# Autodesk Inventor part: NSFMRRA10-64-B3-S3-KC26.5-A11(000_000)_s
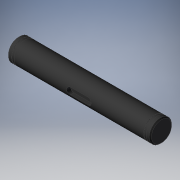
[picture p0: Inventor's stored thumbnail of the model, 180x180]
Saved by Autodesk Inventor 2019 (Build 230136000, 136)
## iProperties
Created: 2022-11
Part Number: NSFMRRA10-64-B3-S3-KC26.5-A11(000_000)_s
Material: Generic
Catalog Web Link: www.cadenas.de
Description: NSFMRR, SFMRR, PSFMRR, SSFMRR, NSFHRR, SFHRR, PSFHRR, SSFHRR, NSFRR, SFRR, PSFRR, SSFRR, NSFMRRA, SFMRRA, PSFMRRA, SSFMRRA, NSFHRRA, SFHRRA, PSFHRRA, SSFHRRA, N
Vendor: MISUMI
Document SubType Name: Modeling
Designer: psAdmin
Manufacturer: MISUMI
Mass: 4.95111 g
Surface Area: 22.1095 cm^2
Volume: 4.95111 cm^3
Density: 1 g/cm^3
Appearance: PSOLRGB-175-175-175
Category: PARTsolutions
Company: MISUMI
Title: NSFMRRA10-64-B3-S3-KC26.5-A11
Author: Cadenas PARTsolutions
Comments: Rotary Shafts - Retaining Ring Grooves on Both Ends - Standard
PSOL_IDENT_0: {$CADENAS_DATA/23d-libs/misumi/metric/11_rotary_shafts/11_components/psfrra/psfrra.prj},808 {VTYP=3D
PSOL_IDENT_1: },{NB=NSFMRRA10-64-B3-S3-KC26.5-A11(000_000)_s},{LINA=NSFMRRA10-64-B3-S3-KC26.5-A11},{NN=NSFMRR, SFM
PSOL_IDENT_2: RR, PSFMRR, SSFMRR, NSFHRR, SFHRR, PSFHRR, SSFHRR, NSFRR, SFRR, PSFRR, SSFRR, NSFMRRA, SFMRRA, PSFMR
PSOL_IDENT_3: RA, SSFMRRA, NSFHRRA, SFHRRA, PSFHRRA, SSFHRRA, NSFRRA, SFRRA, PSFRRA, SSFRRA, HFRRA, PHFRRA, PSFRR
PSOL_IDENT_4: PSFRRA, PSFHRR, PSFHRRA, SSFRR, SSFRRA, SSFHRR, SSFHRRA, PPSFRR, PPSFRRA, PPSFHRR, PPSFHRRA, SSSFRR,
PSOL_IDENT_5: SSSFRRA, SSSFHRR, SSSFHRRA_shaft},{DATE=21.04.2022 07:40:13},{GEOMDATE=27.07.2021 07:13:06},{VERSIO
PSOL_IDENT_6: N=},{LINEID=30},{WBVAR=TS,TYS,MAT,ST,ALT1,L,B,S,ALT2,KC,A,WKC,C,K,E,KZ,Z,ALT3,FC,GALT3,WFC,J,WALT3,V
PSOL_IDENT_7: ,ALT4,SFC,SG,AG,ALT5,UC,ALT7,SC,ALT10,KWC,ALT11,WC,ALT32,CD,ALT34,TCJ,WTCJ,XT,HCJ,WHCJ,XH},{WBNUMERI
PSOL_IDENT_8: C=L,B,S,KC,A,WKC,C,K,E,KZ,Z,FC,GALT3,WFC,J,WALT3,V,SFC,SG,AG,UC,SC,KWC,WC,TCJ,WTCJ,XT,HCJ,WHCJ,XH}
PSOL_IDENT_9: {NB=NSFMRRA10-64-B3-S3-KC26.5-A11(000_000)_s},{LINA=NSFMRRA10-64-B3-S3-KC26.5-A11},{KT=DUMMY},{PN=NS
PSOL_IDENT_10: FMRRA10-64-B3-S3-KC26.5-A11},{TYPE=NSFMRRA},{TS=SWR},{TYS=H9},{TYSALG= 'H9','h9 (Cold-drawn)','H7','
PSOL_IDENT_11: h7 (Ground)','G6','g6 (Ground)' },{MAT=S45C},{MATALG= 'S45C','S45C Equivalent', 'SUS304','SUS304' },
PSOL_IDENT_12: {ST=},{STALG= '','' },{D=10.0},{ALT1=},{ALT1ALG= '','w/o LKC (Changes L Tolerance)','-LKC','with LKC
PSOL_IDENT_13: (Changes L Tolerance)' },{L=64.0},{LALG=[15:800/0.1]},{LMIN=15},{LMAX=800},{NOTE=25},{B=3.0},{BALG=
PSOL_IDENT_14: [3:60/0.1]},{BMAX=60},{S=3.0},{SALG=[3:59/0.1]},{SMAX=59},{MM=1.15},{DD=9.6},{ARR=STWS10},{ALT2=KC},
PSOL_IDENT_15: {ALT2ALG= '', 'w/o Key Grooves','KC','with KC (Key Groove)','WKC','with WKC (Two Key Grooves)','KCWK
PSOL_IDENT_16: C','with KC + WKC (Three Key Grooves)','KZ','with KC + WKC + KZ (Four Key Grooves)' },{ALT2PN=-KC26.
PSOL_IDENT_17: 5-A11},{KC=26.5},{KCALG=[0:61/0.1]},{KCMIN=0},{KCMAX=61},{A=11.0},{AALG=[3:37.5/0.1]},{AMIN=3},{AMAX=
PSOL_IDENT_18: 37.5},{WKC=0.0},{WKCALG=[0]},{WKCMIN=0},{WKCMAX=0},{C=0.0},{CALG=[0]},{CMIN=3},{CMAX=0},{K=0.0},{KAL
PSOL_IDENT_19: G=[0]},{KMIN=0},{KMAX=59},{E=0.0},{EALG=[0]},{EMIN=3},{EMAX=62},{KZ=0.0},{KZALG=[0]},{KZMIN=66},{KZM
PSOL_IDENT_20: AX=61},{Z=0.0},{ZALG=[0]},{ZMIN=3},{ZMAX=64},{CIFKC=2},{CIFWKC=1},{CIFK=1},{CIFKZ=2},{PCUT3D=0},{QCU
PSOL_IDENT_21: T3D=0},{BB=3},{BBALT2=3},{TT=1.8},{TTALT2=1.8},{ALT3=},{ALT3ALG= '', 'w/o Set Screw Flat','FC','with
PSOL_IDENT_22: FC (Adds a Set Screw Flat)','WFC','with WFC (Adds Two Set Screw Flats)','FCWFC','with FC + WFC (Add
PSOL_IDENT_23: s Three Set Screw Flats)' },{ALT3PN=},{FC=0},{FCALG=[0]},{FCMIN=0},{FCMAX=63},{GALT3=0},{GALT3ALG=[0
PSOL_IDENT_24: ]},{GALT3MIN=1},{GALT3MAX=64},{GALT3MAX2=58},{GALT3MAX3=61},{WFC=0},{WFCALG=[0]},{WFCMIN=0},{WFCMIN2=
PSOL_IDENT_25: 2},{WFCMAX=60},{WFCMAX2=-3},{WFCMAX3=-4},{J=0},{JALG=[0]},{JMIN=1},{JMAX=61},{JMAX2=-2},{JMAX3=-5},{
PSOL_IDENT_26: WALT3=0},{WALT3ALG=[0]},{WALT3MIN=0},{WALT3MIN2=66},{WALT3MAX=61},{WALT3MAX2=61},{V=0},{VALG=[0]},{V
PSOL_IDENT_27: MIN=1},{VMAX=62},{VMAX2=62},{CIFFC=0},{H=0},{ALT4=},{ALT4ALG= '', 'w/o SFC (2 Set Screw Flats (Angle
PSOL_IDENT_28: Specified))', 'SFC'  , 'with SFC (2 Set Screw Flats (Angle Specified))'},{ALT4PN=},{SFC=0},{SFCALG=
PSOL_IDENT_29: [0]},{SFCMIN=0},{SFCMAX=63},{SG=0},{SGALG=[0]},{SGMIN=1},{SGMAX=64},{AG=0},{AGALG=[0]},{CIFSFC=0},{A
PSOL_IDENT_30: LT5=},{ALT5ALG= '', 'w/o UC (Slit Cam Groove)', 'UC', 'with UC (Slit Cam Groove)'},{ALT5PN=},{UC=0},
PSOL_IDENT_31: {UCALG=[0]},{UCMIN=1},{UCMAX=58},{DDALT5=8},{LL1=0},{ALT7=},{ALT7ALG= '', 'w/o SC (Wrench Flats)', '
PSOL_IDENT_32: SC', 'with SC (Wrench Flats)'},{ALT7PN=},{SC=0},{SCALG=[0]},{SCMIN=0},{SCMAX=64},{WALT7=0},{LL2=0},{
PSOL_IDENT_33: CIFSC=0},{ALT10=},{ALT10ALG= '','Not applicable' },{ALT10PN=},{KWC=0},{KWCALG=[0]},{KWCMIN=1},{KWCMA
PSOL_IDENT_34: X=0},{WALT10=8},{ALT11=},{ALT11ALG= '','Not applicable' },{ALT11PN=},{WC=0.0},{WCALG=[0]},{ALT32=},{
PSOL_IDENT_35: ALT32ALG=  '','w/o CD (Changes Part D Chamfering)','-CD', 'with CD (Changes Part D Chamfering)' },{C
PSOL_IDENT_36: D=},{CDALG= '','N/A' },{CD3D=0.5},{CIF32=0},{CIF320=0},{CIF32B=0},{CIF32S=0},{ALT32PN=},{ERRORPN=},{
PSOL_IDENT_37: ERRORRALT2=OK},{ERRORRALT3=OK},{ERRORRALT4=NG},{ERRORRALT5=NG},{ERRORRALT7=NG},{ERRORRALT10=OK},{ERR
PSOL_IDENT_38: ORALT23=OK},{ERRORALT24=OK},{ERRORALT25=OK},{ERRORALT27=OK},{ERRORALT210=OK},{ERRORALT34=OK},{ERRORA
PSOL_IDENT_39: LT35=OK},{ERRORALT37=OK},{ERRORALT310=OK},{ERRORALT45=OK},{ERRORALT47=OK},{ERRORALT410=OK},{ERRORALT
PSOL_IDENT_40: 75=OK},{ERRORALT510=OK},{ERRORALT710=OK},{ALT34=},{ALT34ALG= '','Not applicable'},{TCJ=0},{WTCJ=0},{
PSOL_IDENT_41: XT=0},{TM=4},{TCJALG=[0]},{TCJMIN=7.000},{TCJMAX=29.000},{TCJMAX1=29.000},{HCJ=0},{WHCJ=0},{XH=0},{H
PSOL_IDENT_42: P=4},{HCJALG=[0]},{HCJMIN=7.000},{HCJMAX=29.000},{HCJMAX1=29.000},{LCJ=0},{LMINX=15},{XALG=[0]},{XCJ
PSOL_IDENT_43: MIN=7},{WTCJALG=[0]},{WHCJALG=[0]},{XHALG=[0]}
NB: NSFMRRA10-64-B3-S3-KC26.5-A11(000_000)_s
NN: NSFMRR, SFMRR, PSFMRR, SSFMRR, NSFHRR, SFHRR, PSFHRR, SSFHRR, NSFRR, SFRR, PSFRR, SSFRR, NSFMRRA, SFMRRA, PSFMRRA, SSFMRRA, NSFHRRA, SFHRRA, PSFHRRA, SSFHRRA, N
NT: Rotary Shafts - Retaining Ring Grooves on Both Ends - Standard
NBSYN: $PN.($ALT34.$TCJ.$WTCJ.$XT._$HCJ.$WHCJ.$XH.)_s
LINA: NSFMRRA10-64-B3-S3-KC26.5-A11
CATALOG: Misumi
PN: NSFMRRA10-64-B3-S3-KC26.5-A11
TS: With Retaining Ring
TYS: h9 (Cold-drawn)
MAT: S45C Equivalent
D: 10
ALT1: w/o LKC (Changes L Tolerance)
L: 64
B: 3
S: 3
MM: 1.15
DD: 9.6
ALT2: with KC (Key Groove)
KC: 26.5
A: 11
WKC: 0
C: 0
K: 0
E: 0
KZ: 0
Z: 0
ALT3: w/o Set Screw Flat
FC: 0
GALT3: 0
WFC: 0
J: 0
WALT3: 0
V: 0
ALT4: w/o SFC (2 Set Screw Flats (Angle Specified))
SFC: 0
SG: 0
AG: 0
ALT5: w/o UC (Slit Cam Groove)
UC: 0
ALT7: w/o SC (Wrench Flats)
SC: 0
ALT10: Not applicable
KWC: 0
ALT11: Not applicable
WC: 0
ALT32: w/o CD (Changes Part D Chamfering)
CD: N/A
ALT34: Not applicable
TCJ: 0
WTCJ: 0
XT: 0
HCJ: 0
WHCJ: 0
XH: 0
SUPPLIER: MISUMI
ARTICLENO: NSFMRRA10-64-B3-S3-KC26.5-A11(000_000)_s
BOMINFO: NSFMRRA10-64-B3-S3-KC26.5-A11
CREATOR: CADENAS GmbH
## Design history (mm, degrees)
sketch "Sketch_1"
  geometry: L1 (64, 0)-(0, 0); L2 (0, 0)-(0, 4.5); L3 (0, 4.5)-(0.5, 5); L4 (0.5, 5)-(63.5, 5); L5 (63.5, 5)-(64, 4.5); L6 (64, 4.5)-(64, 0); L7 (64, 0)-(0, 0)
  constraints: 14 end point
revolve "Revolution1" sketch "Sketch_1" stored, may be unused: angle "d0" = 360 deg
sketch "_____10"
  geometry: L1 (28, -1.5)-(36, -1.5); L2 (36, 1.5)-(28, 1.5); A1 r 1.5 centre (28, 0) between (28, 1.5) and (28, -1.5); A2 r 1.5 centre (36, 0) between (36, -1.5) and (36, 1.5)
  constraints: 4 end point, 4 point on circle, 2 centre point
extrude "Extrusion1" cut sketch "_____10" distance "d1" = 1.8; taper "d2" = 0 deg
sketch "_____5"
  geometry: C1 r 10 at (0, 0); C2 r 4.8 at (0, 0); 2 further points
  constraints: 2 centre point
extrude "Extrusion2" cut sketch "_____5" distance "d3" = 1.15; taper "d4" = 0 deg
sketch "_____6"
  geometry: C1 r 10 at (0, 0); C2 r 4.8 at (0, 0); 2 further points
  constraints: 2 centre point
extrude "Extrusion3" cut sketch "_____6" distance "d5" = 1.15; taper "d6" = 0 deg
node "COMBINATION_MODULE_XY"
node "COMBINATION_MODULE_YZ"
node "COMBINATION_MODULE_ZX"
node "COMBINATION_MODULE_X"
node "COMBINATION_MODULE_Y"
node "COMBINATION_MODULE_Z"
node "COMBINATION_MODULE_Center"
node "to_ring_b_XY"
node "to_ring_b_YZ"
node "to_ring_b_ZX"
node "to_ring_b_X"
node "to_ring_b_Y"
node "to_ring_b_Z"
node "to_ring_b_Center"
node "to_ring_s_XY"
node "to_ring_s_YZ"
node "to_ring_s_ZX"
node "to_ring_s_X"
node "to_ring_s_Y"
node "to_ring_s_Z"
node "to_ring_s_Center"
body "Solid1"
other parameters: "d7" = 0
